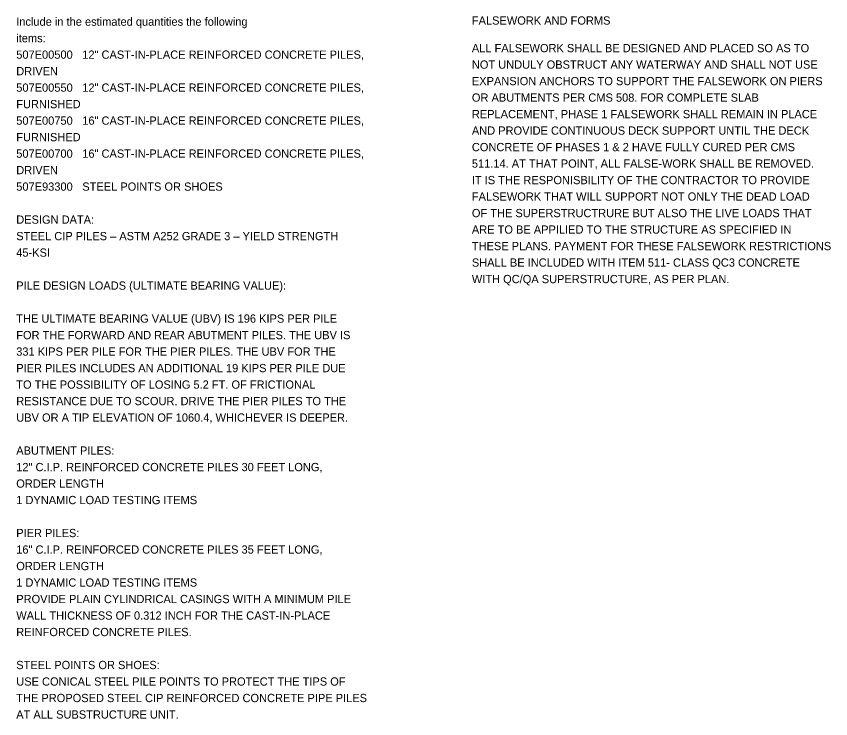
# Model space of a CAD drawing. Extents: x -15 to 144, y -80 to 40.
# Drawn here: x 22.43 to 36.24, y -14.21 to -2.29 of the extents above; entities that cross this region are included whole.
import ezdxf

# ---------------------------------------------------------------- set-up
doc = ezdxf.new("R2010")
doc.units = 0
doc.layers.add('BR_P_Gen_Text', color=7, linetype='Continuous')

msp = doc.modelspace()

# ---------------------------------------------------------------- texts
at = {"layer": 'BR_P_Gen_Text'}
for s, p in [('Include in the estimated quantities the following ', (22.425, -2.453)), ('FALSEWORK AND FORMS', (30.154, -2.434)), ('items:', (22.425, -2.733)), ('ALL FALSEWORK SHALL BE DESIGNED AND PLACED SO AS TO ', (30.154, -2.902)), ('507E00500', (22.425, -3.013)), ('12" CAST-IN-PLACE REINFORCED CONCRETE PILES, ', (23.545, -3.013)), ('DRIVEN', (22.425, -3.293)), ('NOT UNDULY OBSTRUCT ANY WATERWAY AND SHALL NOT USE ', (30.154, -3.182)), ('507E00550', (22.425, -3.573)), ('12" CAST-IN-PLACE REINFORCED CONCRETE PILES, ', (23.545, -3.573)), ('EXPANSION ANCHORS TO SUPPORT THE FALSEWORK ON PIERS ', (30.154, -3.462)), ('FURNISHED ', (22.425, -3.853)), ('OR ABUTMENTS PER CMS 508. FOR COMPLETE SLAB ', (30.154, -3.742)), ('507E00750', (22.425, -4.133)), ('16" CAST-IN-PLACE REINFORCED CONCRETE PILES, ', (23.545, -4.133)), ('REPLACEMENT, PHASE 1 FALSEWORK SHALL REMAIN IN PLACE ', (30.154, -4.022)), ('FURNISHED', (22.425, -4.413)), ('AND PROVIDE CONTINUOUS DECK SUPPORT UNTIL THE DECK ', (30.154, -4.302)), ('507E00700', (22.425, -4.693)), ('16" CAST-IN-PLACE REINFORCED CONCRETE PILES, ', (23.545, -4.693)), ('CONCRETE OF PHASES 1 & 2 HAVE FULLY CURED PER CMS ', (30.154, -4.582)), ('DRIVEN', (22.425, -4.973)), ('511.14. AT THAT POINT, ALL FALSE-WORK SHALL BE REMOVED. ', (30.154, -4.862)), ('507E93300', (22.425, -5.253)), ('STEEL POINTS OR SHOES', (23.545, -5.253)), ('IT IS THE RESPONISBILITY OF THE CONTRACTOR TO PROVIDE ', (30.154, -5.142)), ('FALSEWORK THAT WILL SUPPORT NOT ONLY THE DEAD LOAD ', (30.154, -5.422)), ('OF THE SUPERSTRUCTRURE BUT ALSO THE LIVE LOADS THAT ', (30.154, -5.702)), ('DESIGN DATA:', (22.425, -5.813)), ('ARE TO BE APPILIED TO THE STRUCTURE AS SPECIFIED IN ', (30.154, -5.982)), ('STEEL CIP PILES – ASTM A252 GRADE 3 – YIELD STRENGTH ', (22.425, -6.093)), ('THESE PLANS. PAYMENT FOR THESE FALSEWORK RESTRICTIONS ', (30.154, -6.262)), ('45-KSI', (22.425, -6.373)), ('SHALL BE INCLUDED WITH ITEM 511- CLASS QC3 CONCRETE ', (30.154, -6.542)), ('WITH QC/QA SUPERSTRUCTURE, AS PER PLAN. ', (30.154, -6.822)), ('PILE DESIGN LOADS (ULTIMATE BEARING VALUE): ', (22.425, -6.933)), ('THE ULTIMATE BEARING VALUE (UBV) IS 196 KIPS PER PILE ', (22.425, -7.493)), ('FOR THE FORWARD AND REAR ABUTMENT PILES. THE UBV IS ', (22.425, -7.773)), ('331 KIPS PER PILE FOR THE PIER PILES. THE UBV FOR THE ', (22.425, -8.053)), ('PIER PILES INCLUDES AN ADDITIONAL 19 KIPS PER PILE DUE ', (22.425, -8.333)), ('TO THE POSSIBILITY OF LOSING 5.2 FT. OF FRICTIONAL ', (22.425, -8.613)), ('RESISTANCE DUE TO SCOUR. DRIVE THE PIER PILES TO THE ', (22.425, -8.893)), ('UBV OR A TIP ELEVATION OF 1060.4, WHICHEVER IS DEEPER.', (22.425, -9.173)), ('ABUTMENT PILES:', (22.425, -9.733)), ('12" C.I.P. REINFORCED CONCRETE PILES 30 FEET LONG, ', (22.425, -10.013)), ('ORDER LENGTH', (22.425, -10.293)), ('1 DYNAMIC LOAD TESTING ITEMS', (22.425, -10.573)), ('PIER PILES:', (22.425, -11.133)), ('16" C.I.P. REINFORCED CONCRETE PILES 35 FEET LONG, ', (22.425, -11.413)), ('ORDER LENGTH', (22.425, -11.693)), ('1 DYNAMIC LOAD TESTING ITEMS', (22.425, -11.973)), ('PROVIDE PLAIN CYLINDRICAL CASINGS WITH A MINIMUM PILE ', (22.425, -12.253)), ('WALL THICKNESS OF 0.312 INCH FOR THE CAST-IN-PLACE ', (22.425, -12.533)), ('REINFORCED CONCRETE PILES.', (22.425, -12.813)), ('STEEL POINTS OR SHOES:', (22.425, -13.373)), ('USE CONICAL STEEL PILE POINTS TO PROTECT THE TIPS OF ', (22.425, -13.653)), ('THE PROPOSED STEEL CIP REINFORCED CONCRETE PIPE PILES ', (22.425, -13.933)), ('AT ALL SUBSTRUCTURE UNIT.', (22.425, -14.213))]:
    msp.add_text(s, height=0.14, dxfattribs=at).set_placement(p)

doc.saveas('drawing.dxf')
